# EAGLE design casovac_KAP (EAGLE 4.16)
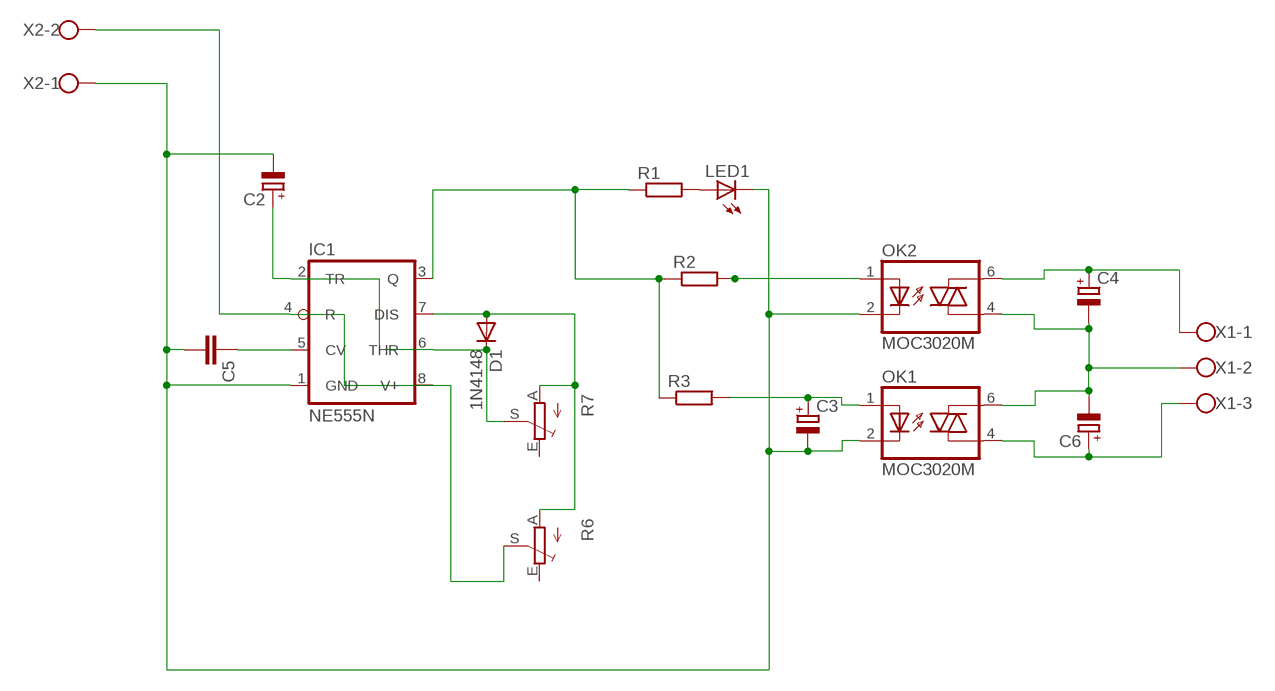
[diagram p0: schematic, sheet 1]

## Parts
C2  CPOL-EUSANYO_F13  [SANYO-OSCON_F13]
C3  CPOL-EUSANYO_E13  [SANYO-OSCON_E13]
C4  CPOL-EUE5-5  [E5-5]
C5  C-EU050-025X075  [C050-025X075]
C6  CPOL-EUE5-5  [E5-5]
D1  1N4148  [DO35-10]
IC1  NE555N  [DIL08]
LED1  LED5MM  [LED5MM]
OK1  MOC3020M  [DIL06]
OK2  MOC3020M  [DIL06]
R1  R-EU_0207/12  [0207/12]
R2  R-EU_0207/12  [0207/12]
R3  R-EU_0207/12  [0207/12]
R6  TRIM_EU-CA9V  [CA9V]
R7  TRIM_EU-CA9V  [CA9V]
X1  W237-103  [W237-103]
X2  W237-102  [W237-102]

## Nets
GND: C2.- C3.- C5.2 IC1.1(GND) LED1.K(C) OK1.2(C) OK2.2(C) X2.1
N$1: C6.+ OK1.4(A1) X1.3
N$2: C4.- C6.- OK1.6(A2) OK2.4(A1) X1.2
N$3: LED1.A R1.2
N$4: C4.+ OK2.6(A2) X1.1
N$5: OK2.1(A) R2.2
N$8: C3.+ OK1.1(A) R3.2
N$10: C2.+ D1.C IC1.2(TR) IC1.6(THR) R7.S
N$11: IC1.3(Q) R1.1 R2.1 R3.1
N$12: C5.1 IC1.5(CV)
N$14: D1.A IC1.7(DIS) R6.A R7.A
VCC: IC1.4(R) IC1.8(V+) R6.S X2.2
Unconnected: R6.E R7.E

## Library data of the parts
C2-C4 C6 = rcl:CPOL-EU: POLARIZED CAPACITOR, European symbol
C5 = rcl:C-EU: CAPACITOR, European symbol
D1 = diode:1N4148: DIODE
IC1 = linear:*555: TIMER
LED1 = led:LED: LED
OK1 OK2 = optocoupler:MOC30*M: RANDOM-PHASE OPTOISOLATORS TRIAC DRIVER OUTPUT Source: http://www.fairchildsemi.com MOC3020-M.pdf
R1-R3 = rcl:R-EU_: RESISTOR, European symbol
R6 R7 = pot:TRIM_EU-: POTENTIOMETER
X1 = con-wago-500:W237-103: WAGO SCREW CLAMP
X2 = con-wago-500:W237-102: WAGO SCREW CLAMP

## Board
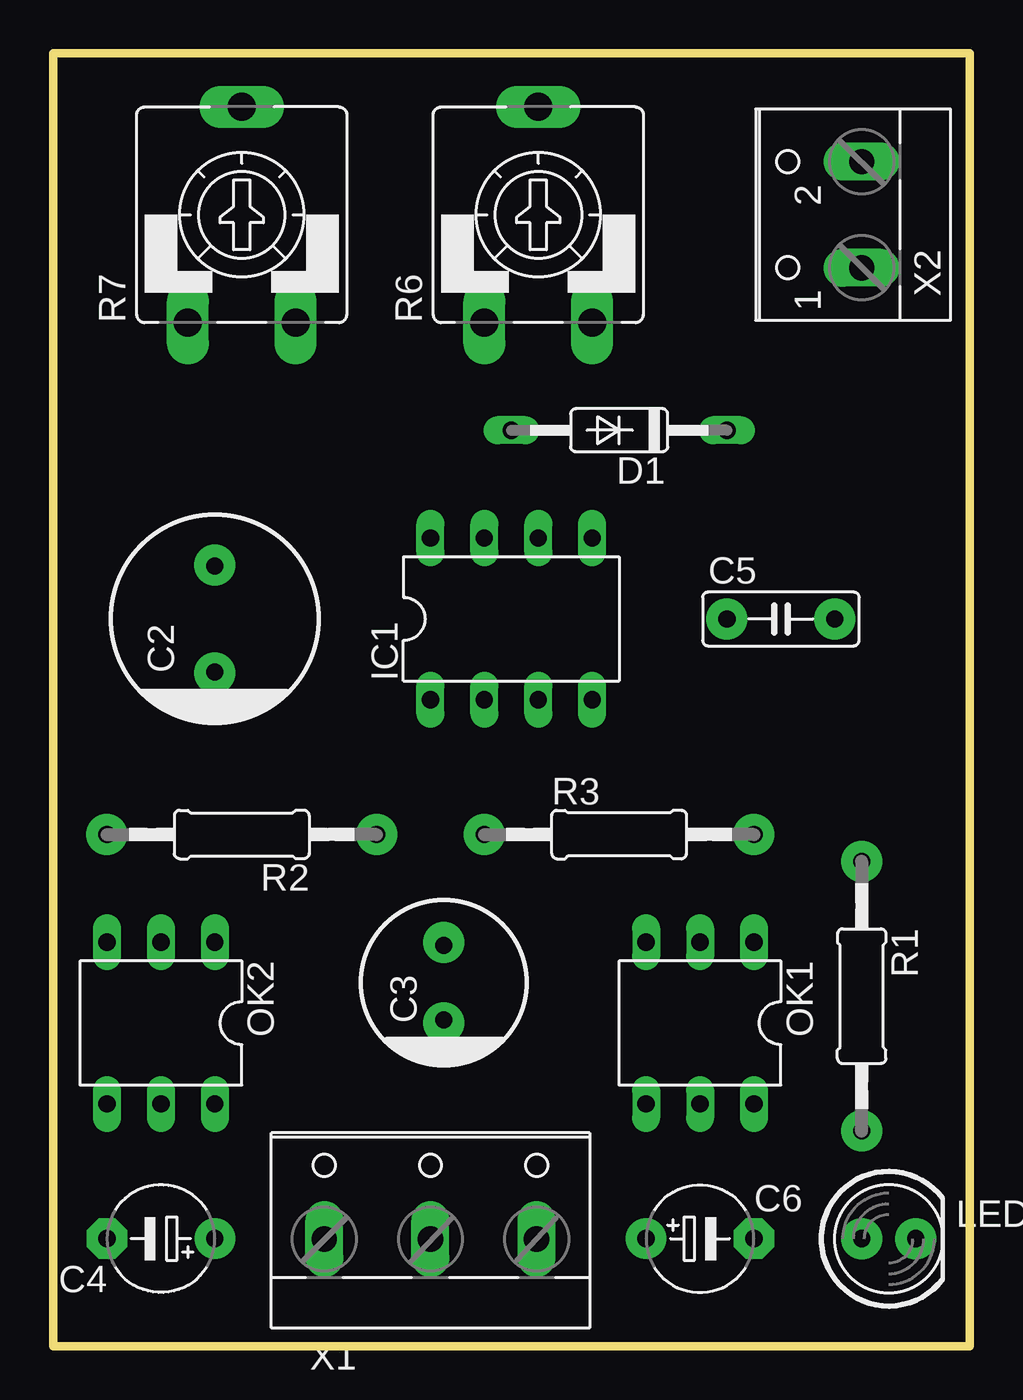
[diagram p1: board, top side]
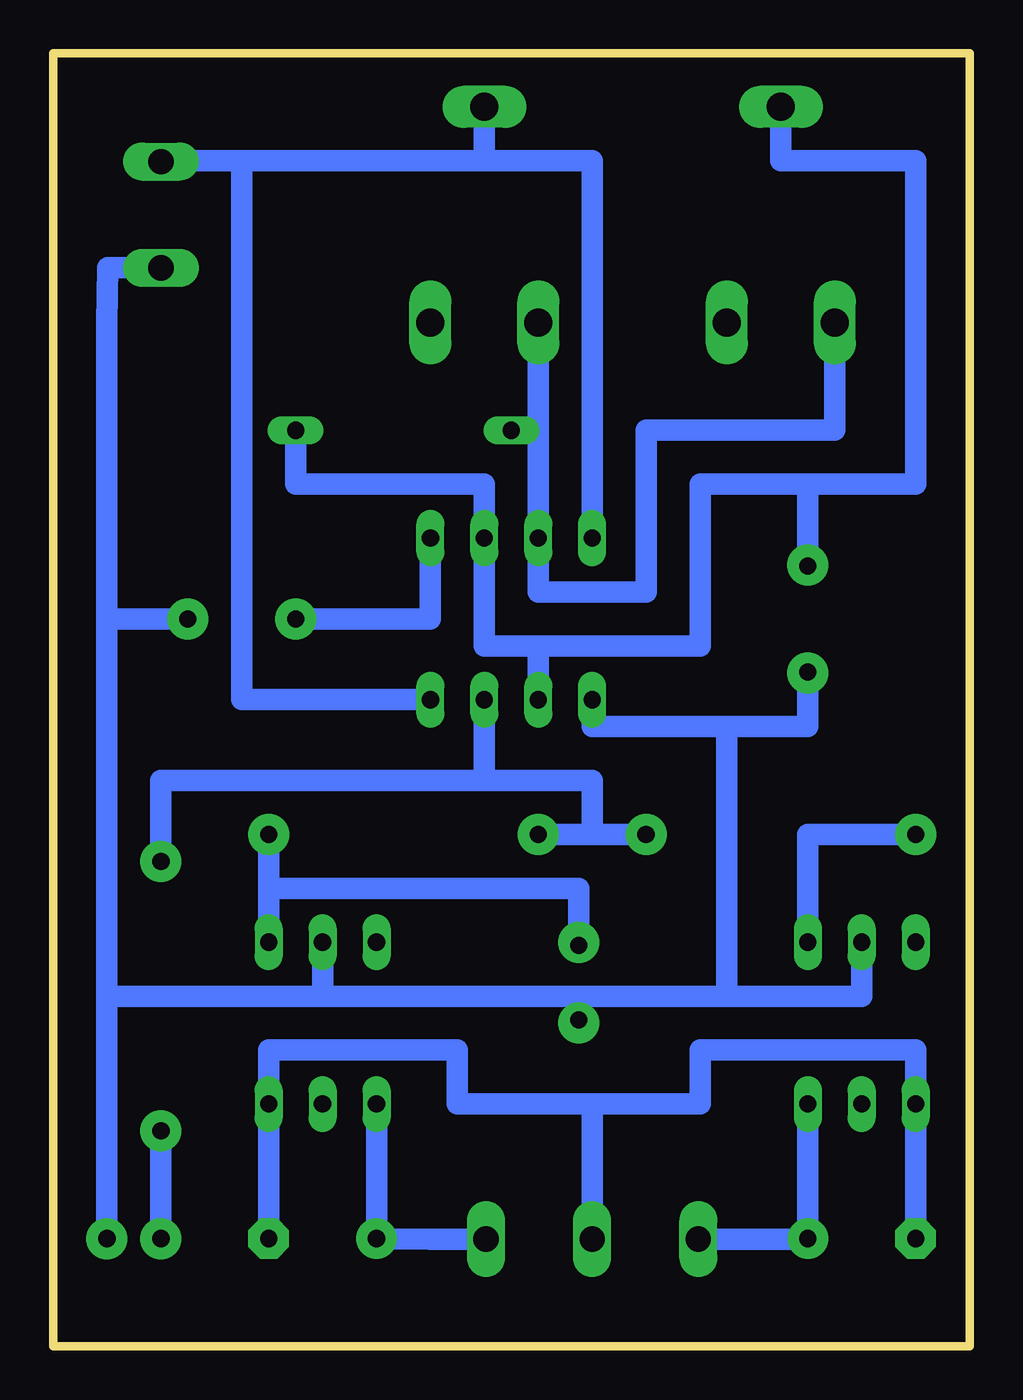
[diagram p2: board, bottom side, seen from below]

Size 43.18 x 60.96 mm. Coordinates in mm from the lower left corner, seen from the top.
Outline: 0,0 43.18,0 43.18,60.96 0,60.96 0,0
Copper layers (1*16): Top 0.035mm / dielectric 1.5mm / Bottom 0.035mm
Design rules "default": minimum track width 10mil, minimum drill 24mil, track to track 8mil, track to pad 8mil, pad to pad 8mil, via to via 8mil, smd to smd 8mil, copper to edge 40mil, drill to drill 8mil, minimum pad ring 10mil, minimum via ring 8mil, stop-mask expansion 4mil, vias tented up to drill 0mil, thermal gap 10mil

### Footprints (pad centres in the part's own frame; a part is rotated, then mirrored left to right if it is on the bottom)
SANYO-OSCON_F13 = drill 0.8 pad 1.27 round: + 2.5,0; - -2.5,0
SANYO-OSCON_E13 = drill 0.8 pad 1.27 round: + 1.75,0; - -1.75,0
E5-5 = drill 0.813 pad 1.905 round: + -2.54,0 | drill 0.813 pad 1.905 octagon: - 2.54,0
C050-025X075 = drill 0.813 octagon: 1 -2.54,0; 2 2.54,0
DO35-10 = drill 0.813 long: A 5.08,0; C -5.08,0
DIL08 = drill 0.813 long: 1 -3.81,-3.81; 2 -1.27,-3.81; 3 1.27,-3.81; 4 3.81,-3.81; 5 3.81,3.81; 6 1.27,3.81; 7 -1.27,3.81; 8 -3.81,3.81
LED5MM = drill 0.813 octagon: A -1.27,0; K 1.27,0
DIL06 = drill 0.813 long: 1 -2.54,-3.81; 2 0,-3.81; 3 2.54,-3.81; 4 2.54,3.81; 5 0,3.81; 6 -2.54,3.81
0207/12 = drill 0.813 octagon: 1 -6.35,0; 2 6.35,0
CA9V = drill 1.321 long: A -2.54,-5.08; E 2.54,-5.08; S 0,5.08
W237-103 = drill 1.194 long: 1 -5,-1.29; 2 0,-1.29; 3 5,-1.29
W237-102 = drill 1.194 long: 1 -2.5,-1.27; 2 2.5,-1.27

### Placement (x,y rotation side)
C2  7.62,34.29 90 top
C3  18.41,17.14 90 top
C4  5.08,5.08 180 top
C5  34.29,34.29 0 top
C6  30.48,5.08 0 top
D1  26.67,43.18 180 top
IC1  21.59,34.29 0 top
LED1  39.37,5.08 0 top
OK1  30.48,15.24 180 top
OK2  5.08,15.24 180 top
R1  38.1,16.51 270 top
R2  8.89,24.13 180 top
R3  26.67,24.13 0 top
R6  22.86,53.34 0 top
R7  8.89,53.34 0 top
X1  17.78,6.35 0 top
X2  36.83,53.34 90 top

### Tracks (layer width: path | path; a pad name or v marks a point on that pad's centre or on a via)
GND  (via drill 0.5 pad 1.93)
  Bottom 1.016: OK2.2 5.08,16.51 11.43,16.51 | 11.43,16.51 18.41,16.51 | v18.41,15.24 18.41,16.51 | 18.41,16.51 30.48,16.51 | 30.48,16.51 OK1.2 | 30.48,16.51 40.64,16.51 | 11.43,29.21 17.78,29.21 IC1.1 | 18.41,16.51 C3.- | 40.64,16.51 LED1.K | 40.64,16.51 40.64,34.29 | 40.64,34.29 40.64,48.26 40.6,50.84 X2.1 | 11.43,29.21 7.62,29.21 v7.62,31.75 C2.- | 11.43,16.51 11.43,29.21 | 40.64,34.29 C5.2
  other vias: 40.64,5.08 36.83,34.29
N$1
  Bottom 0.406: C6.+ OK1.4
  Bottom 1.016: X1.3 25.4,5.06 C6.+ OK1.4
N$2
  Bottom 0.406: X1.2 17.78,5.08
  Bottom 1.016: 2.54,13.97 OK2.4 | 2.54,13.97 C4.- | 2.54,13.97 12.7,13.97 12.7,11.43 17.78,11.43 | 17.78,11.43 X1.2 | 17.78,11.43 24.13,11.43 24.13,13.97 33.02,13.97 C6.- OK1.6
N$3  (via drill 0.5 pad 1.93)
  Bottom 1.016: R1.2 LED1.A
  other vias: 38.1,5.08 38.1,10.16
N$4
  Bottom 1.016: 7.62,5.06 X1.1 | C4.+ 7.62,5.06 | 7.62,5.06 OK2.6
N$5  (via drill 0.5 pad 1.93)
  Bottom 1.016: R2.2 7.62,24.13 OK2.1
  other vias: 2.54,24.13
N$8  (via drill 0.5 pad 1.93)
  Bottom 1.016: 33.02,21.59 OK1.1 | 33.02,21.59 18.41,21.59 v18.41,19.05 C3.+ | 33.02,21.59 R3.2
  other vias: 33.02,24.13
N$10  (via drill 0.5 pad 1.93)
  Bottom 1.016: 20.32,33.02 IC1.2 | 20.32,33.02 12.7,33.02 12.7,40.64 7.62,40.64 | 20.32,33.02 22.86,33.02 IC1.6 22.86,40.64 31.75,40.64 D1.C | R7.S 8.89,55.88 2.54,55.88 2.54,40.64 7.62,40.64 | 7.62,40.64 v7.62,36.83 C2.+
N$11  (via drill 0.5 pad 1.93)
  Bottom 1.016: 22.86,26.67 IC1.3 | 22.86,26.67 38.1,26.67 R1.1 | 17.78,24.13 R3.1 | R2.1 17.78,24.13 | 17.78,24.13 17.78,26.67 22.86,26.67
  other vias: 38.1,22.86 15.24,24.13 20.32,24.13
N$12  (via drill 0.5 pad 1.93)
  Bottom 1.016: IC1.5 25.4,34.29 C5.1
  other vias: 31.75,34.29
N$14
  Bottom 1.016: 20.32,43.18 IC1.7 20.32,35.56 15.24,35.56 15.24,43.18 6.35,43.18 R7.A | 20.32,43.18 D1.A | 20.32,43.18 R6.A
VCC
  Bottom 1.016: IC1.8 17.78,55.88 22.86,55.88 | IC1.4 34.29,30.48 34.29,55.88 | 22.86,55.88 34.29,55.88 | 22.86,55.88 R6.S | X2.2 38.1,55.88 34.29,55.88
